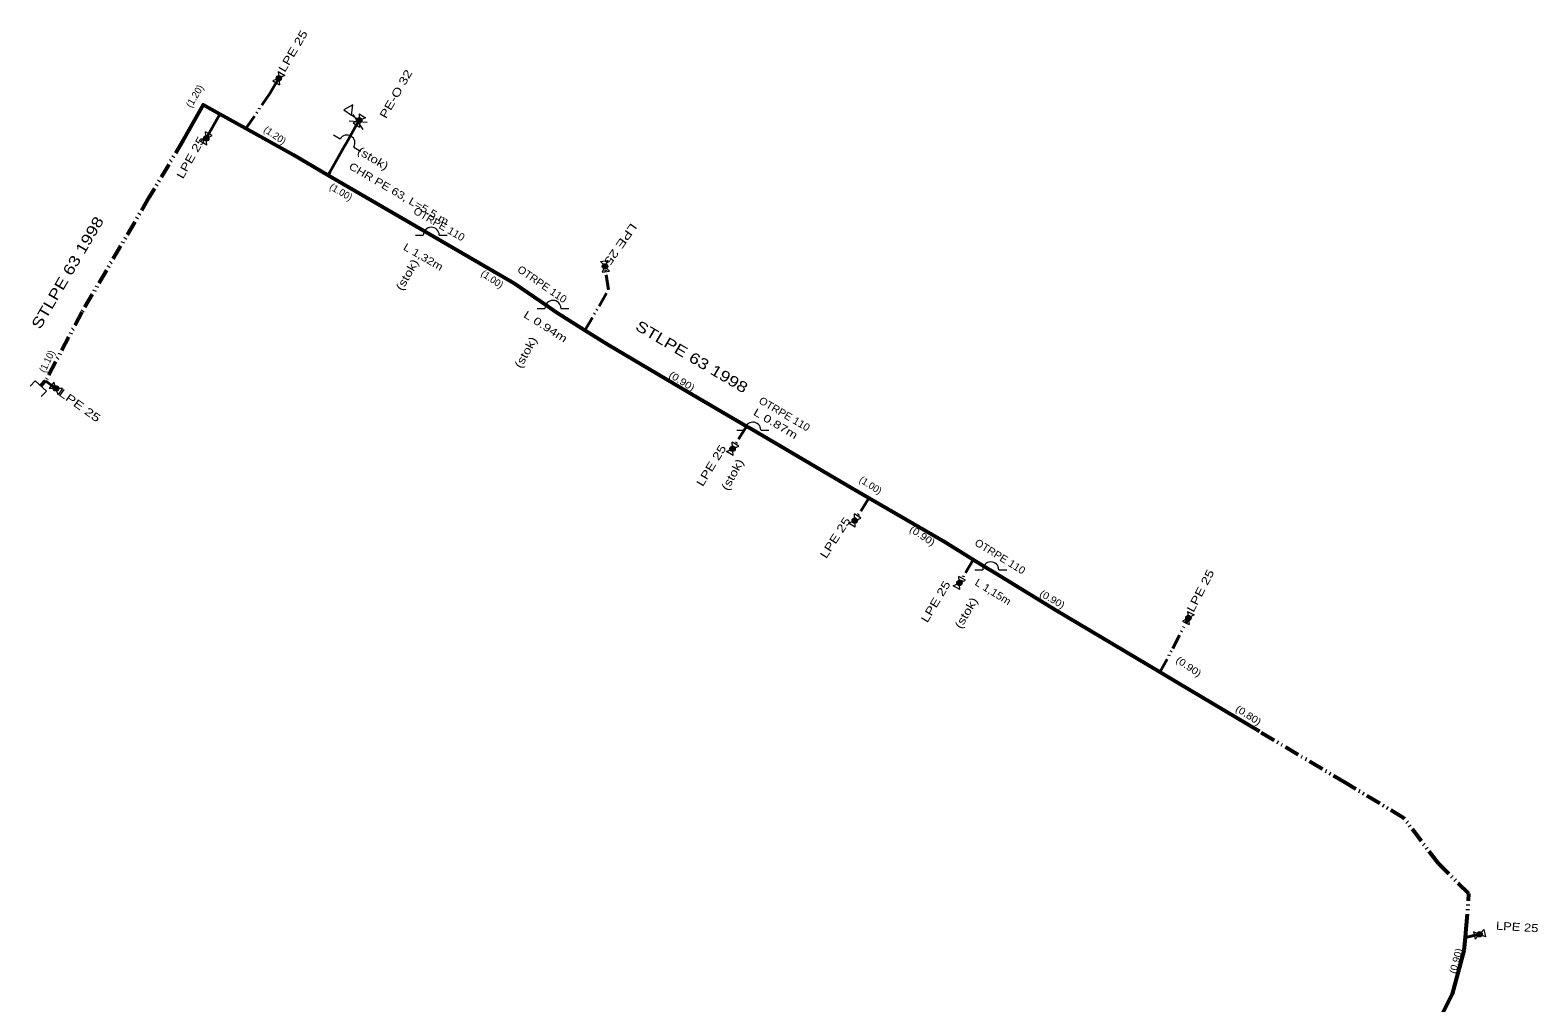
# Model space of a CAD drawing. Extents: x -648036 to -642998, y -1161549 to -1158141.
# Drawn here: x -647414.4 to -647274.3, y -1158231 to -1158140.6 of the extents above; entities that cross this region are included whole.
import ezdxf
from ezdxf.enums import TextEntityAlignment as Align

# ---------------------------------------------------------------- set-up
doc = ezdxf.new("R2010")
doc.units = 0
doc.header["$LTSCALE"] = 0.28
doc.linetypes.add('DASH_DOUBLE_DOT', pattern=[9.2, 5, -1.2, 0.3, -1.2, 0.3, -1.2])
for name, color, linetype, lineweight in [('12', 7, 'DASH_DOUBLE_DOT', 40), ('14', 7, 'Continuous', 13), ('15', 7, 'Continuous', 13), ('19', 7, 'Continuous', 13), ('8', 7, 'Continuous', 53)]:
    doc.layers.add(name, color=color, linetype=linetype, lineweight=lineweight)
for name, color, linetype in [('20', 7, 'Continuous'), ('22', 7, 'Continuous'), ('24', 7, 'Continuous'), ('27', 7, 'Continuous'), ('28', 7, 'Continuous')]:
    doc.layers.add(name, color=color, linetype=linetype)

msp = doc.modelspace()

# ---------------------------------------------------------------- linework, layer by layer
at = {"layer": '12', "linetype": 'Continuous'}
for p, q in [((-647396.79, -1158148.41), (-647398.06, -1158150.68)), ((-647413, -1158173.22), (-647412.03, -1158173.92))]:
    msp.add_line(p, q, dxfattribs=at)
at = {"layer": '12'}
for p, q in [((-647347.84, -1158177.44), (-647349.13, -1158179.53)), ((-647336.46, -1158184.13), (-647337.78, -1158186.2)), ((-647326.77, -1158189.84), (-647328.05, -1158192)), ((-647281, -1158224.94), (-647279.7, -1158224.65))]:
    msp.add_line(p, q, dxfattribs=at)
for points in [[(-647394.38, -1158149.75), (-647392.15, -1158146.51), (-647391.31, -1158145.08)], [(-647362.86, -1158168.52), (-647360.66, -1158164.74), (-647360.99, -1158162.57)], [(-647309.41, -1158200.3), (-647308.22, -1158198.08), (-647306.76, -1158195.25)]]:
    msp.add_lwpolyline(points, dxfattribs=at)
at = {"layer": '12', "linetype": 'Continuous'}
for points in [[(-647386.71, -1158154.12), (-647386.58, -1158153.81), (-647385.16, -1158151.33), (-647385.02, -1158151.08), (-647383.93, -1158149.15)], [(-647383.93, -1158149.15), (-647383.858, -1158149.042), (-647383.83, -1158149)]]:
    msp.add_lwpolyline(points, dxfattribs=at)
at = {"layer": '14'}
for p, q in [((-647376.52, -1158160.05), (-647377.66, -1158159.39)), ((-647365.56, -1158166.82), (-647366.31, -1158166.3)), ((-647346.9, -1158177.99), (-647347.65, -1158177.55)), ((-647324.73, -1158191.1), (-647325.7, -1158190.5))]:
    msp.add_line(p, q, dxfattribs=at)
msp.add_lwpolyline([(-647383.858, -1158149.042), (-647383.93, -1158149.15), (-647385.02, -1158151.08), (-647385.16, -1158151.33), (-647386.58, -1158153.81)], dxfattribs=at)
at = {"layer": '15'}
for p, q in [((-647390.748, -1158144.826), (-647391.872, -1158145.333)), ((-647391.872, -1158145.333), (-647391.258, -1158145.695)), ((-647391.362, -1158144.465), (-647391.258, -1158145.695)), ((-647391.362, -1158144.465), (-647390.748, -1158144.826)), ((-647383.847, -1158148.383), (-647383.813, -1158149.617)), ((-647383.847, -1158148.383), (-647383.254, -1158148.778)), ((-647383.093, -1158149.211), (-647384.766, -1158149.089)), ((-647383.83, -1158149), (-647384.541, -1158148.521)), ((-647383.254, -1158148.778), (-647384.405, -1158149.221)), ((-647384.405, -1158149.221), (-647383.813, -1158149.617)), ((-647383.472, -1158149.853), (-647384.388, -1158148.448)), ((-647398.617, -1158150.946), (-647397.504, -1158150.415)), ((-647397.995, -1158151.294), (-647398.617, -1158150.946)), ((-647397.504, -1158150.415), (-647398.125, -1158150.066)), ((-647397.995, -1158151.294), (-647398.125, -1158150.066)), ((-647386.242, -1158150.347), (-647385.613, -1158150.726)), ((-647384.341, -1158151.495), (-647383.713, -1158151.876)), ((-647378.615, -1158159.685), (-647377.88, -1158159.684)), ((-647376.394, -1158159.684), (-647375.66, -1158159.685)), ((-647361.418, -1158162.125), (-647360.714, -1158162.018)), ((-647361.418, -1158162.125), (-647360.562, -1158163.015)), ((-647360.714, -1158162.018), (-647361.266, -1158163.121)), ((-647361.266, -1158163.121), (-647360.562, -1158163.015)), ((-647367.305, -1158166.475), (-647366.57, -1158166.474)), ((-647365.084, -1158166.474), (-647364.35, -1158166.475)), ((-647412.23, -1158173.337), (-647412.647, -1158173.914)), ((-647411.83, -1158174.504), (-647412.23, -1158173.337)), ((-647411.413, -1158173.926), (-647412.647, -1158173.914)), ((-647411.413, -1158173.926), (-647411.83, -1158174.504)), ((-647348.725, -1158177.795), (-647347.99, -1158177.794)), ((-647346.504, -1158177.794), (-647345.77, -1158177.795)), ((-647348.563, -1158179.289), (-647349.168, -1158178.914)), ((-647349.092, -1158180.146), (-647349.168, -1158178.914)), ((-647349.698, -1158179.772), (-647348.563, -1158179.289)), ((-647349.092, -1158180.146), (-647349.698, -1158179.772)), ((-647338.351, -1158186.434), (-647337.209, -1158185.967)), ((-647337.209, -1158185.967), (-647337.809, -1158185.584)), ((-647337.751, -1158186.816), (-647337.809, -1158185.584)), ((-647337.751, -1158186.816), (-647338.351, -1158186.434)), ((-647328.613, -1158192.252), (-647327.487, -1158191.749)), ((-647327.487, -1158191.749), (-647328.099, -1158191.385)), ((-647328.001, -1158192.615), (-647328.099, -1158191.385)), ((-647326.605, -1158190.785), (-647325.87, -1158190.784)), ((-647324.384, -1158190.784), (-647323.65, -1158190.785)), ((-647328.001, -1158192.615), (-647328.613, -1158192.252)), ((-647306.845, -1158194.639), (-647306.675, -1158195.861)), ((-647306.845, -1158194.639), (-647306.213, -1158194.965)), ((-647306.213, -1158194.965), (-647307.307, -1158195.534)), ((-647307.307, -1158195.534), (-647306.675, -1158195.861)), ((-647280.268, -1158224.412), (-647280.114, -1158225.107)), ((-647279.131, -1158224.888), (-647280.268, -1158224.412)), ((-647279.286, -1158224.193), (-647280.114, -1158225.107)), ((-647279.286, -1158224.193), (-647279.131, -1158224.888))]:
    msp.add_line(p, q, dxfattribs=at)
msp.add_lwpolyline([(-647384.541, -1158148.521), (-647384.422, -1158147.567), (-647385.262, -1158148.035)], close=True, dxfattribs=at)
msp.add_lwpolyline([(-647414.426, -1158173.714), (-647413.946, -1158173.198), (-647412.914, -1158174.162), (-647413.396, -1158174.677)], dxfattribs=at)
for centre, start, end in [((-647384.9774, -1158151.1112), 330.11164, 148.67634), ((-647377.1374, -1158159.6846), 1.2748, 179.83951), ((-647365.8274, -1158166.4746), 1.2748, 179.83951), ((-647347.2474, -1158177.7946), 1.2748, 179.83951), ((-647325.1274, -1158190.7846), 1.2748, 179.83951)]:
    msp.add_arc(centre, 0.7431, start, end, dxfattribs=at)
at = {"layer": '19'}
for centre, radius in [((-647391.31, -1158145.08), 0.25), ((-647391.31, -1158145.08), 0.17), ((-647391.31, -1158145.08), 0.09), ((-647383.83, -1158149), 0.25), ((-647383.83, -1158149), 0.17), ((-647383.83, -1158149), 0.09), ((-647398.06, -1158150.68), 0.25), ((-647398.06, -1158150.68), 0.17), ((-647398.06, -1158150.68), 0.09), ((-647360.99, -1158162.57), 0.25), ((-647360.99, -1158162.57), 0.17), ((-647360.99, -1158162.57), 0.09), ((-647412.03, -1158173.92), 0.25), ((-647412.03, -1158173.92), 0.17), ((-647412.03, -1158173.92), 0.09), ((-647349.13, -1158179.53), 0.25), ((-647349.13, -1158179.53), 0.17), ((-647349.13, -1158179.53), 0.09), ((-647337.78, -1158186.2), 0.25), ((-647337.78, -1158186.2), 0.17), ((-647337.78, -1158186.2), 0.09), ((-647328.05, -1158192), 0.25), ((-647328.05, -1158192), 0.17), ((-647328.05, -1158192), 0.09), ((-647306.76, -1158195.25), 0.25), ((-647306.76, -1158195.25), 0.17), ((-647306.76, -1158195.25), 0.09), ((-647279.7, -1158224.65), 0.25), ((-647279.7, -1158224.65), 0.17), ((-647279.7, -1158224.65), 0.09)]:
    msp.add_circle(centre, radius, dxfattribs=at)
at = {"layer": '8', "linetype": 'DASH_DOUBLE_DOT'}
msp.add_line((-647281.12, -1158226.16), (-647281, -1158224.94), dxfattribs=at)
at = {"layer": '8'}
for points in [[(-647396.79, -1158148.41), (-647398.35, -1158147.57), (-647400.09, -1158150.62), (-647400.21, -1158150.85)], [(-647386.71, -1158154.12), (-647389.99, -1158152.21), (-647394.38, -1158149.75), (-647396.79, -1158148.41)], [(-647362.86, -1158168.52), (-647365.56, -1158166.82), (-647366.31, -1158166.3), (-647369.43, -1158164.15), (-647376.52, -1158160.05), (-647377.66, -1158159.39), (-647386.35, -1158154.33), (-647386.71, -1158154.12)], [(-647347.84, -1158177.44), (-647353.75, -1158173.97), (-647360.68, -1158169.9), (-647362.86, -1158168.52)], [(-647336.46, -1158184.13), (-647338.02, -1158183.23), (-647346.9, -1158177.99), (-647347.65, -1158177.55), (-647347.84, -1158177.44)], [(-647326.77, -1158189.84), (-647329.39, -1158188.22), (-647336.46, -1158184.13)], [(-647309.41, -1158200.3), (-647319.12, -1158194.52), (-647324.73, -1158191.1), (-647325.7, -1158190.5), (-647326.77, -1158189.84)], [(-647300.16, -1158205.81), (-647307.7, -1158201.32), (-647309.41, -1158200.3)], [(-647288.32, -1158243.49), (-647286.21, -1158238.41), (-647285.23, -1158236.21), (-647283.79, -1158233.33), (-647282.2, -1158230.19), (-647281.12, -1158226.16)]]:
    msp.add_lwpolyline(points, dxfattribs=at)
at = {"layer": '8', "linetype": 'DASH_DOUBLE_DOT'}
for points in [[(-647400.21, -1158150.85), (-647403.38, -1158156.17), (-647409.63, -1158166.83), (-647413, -1158173.22), (-647413.43, -1158173.68)], [(-647281, -1158224.94), (-647280.93, -1158224.15), (-647280.68, -1158220.87), (-647283.52, -1158218.08), (-647286.73, -1158213.85), (-647292.07, -1158210.65), (-647300.16, -1158205.81)]]:
    msp.add_lwpolyline(points, dxfattribs=at)

# ---------------------------------------------------------------- texts
at = {"layer": '20', "width": 1.25}
for rotation, p in [(59.588, (-647410.5184, -1158163.4066)), (329.451, (-647353.1751, -1158171.4024))]:
    msp.add_text('STLPE 63 1998', height=1, rotation=rotation, dxfattribs=at).set_placement(p, align=Align.CENTER)
at = {"layer": '22'}
for s, rotation, width, p in [('LPE 25', 59.588, 1.3, (-647389.6717, -1158142.7468)), ('PE-O 32', 60.298, 1.3, (-647380.1012, -1158146.7298)), ('LPE 25', 60.734, 1.3, (-647399.1791, -1158152.6358)), ('LPE 25', 234.913, 1.35, (-647359.849, -1158160.3039)), ('LPE 25', 324.294, 1.35, (-647410.0319, -1158175.8047)), ('LPE 25', 58.442, 1.3, (-647350.7947, -1158181.2793)), ('LPE 25', 57.296, 1.3, (-647339.2768, -1158187.9926)), ('LPE 25', 59.015, 1.3, (-647329.9378, -1158193.9236)), ('LPE 25', 62.452, 1.3, (-647305.3069, -1158192.8909)), ('LPE 25', 356.38, 1.2, (-647276.2207, -1158224.3438))]:
    msp.add_text(s, height=0.75, rotation=rotation, dxfattribs=dict(at, width=width)).set_placement(p, align=Align.CENTER)
at = {"layer": '24'}
for s, rotation, width, p in [('CHR PE 63, L=5.5.m', 329.793, 1.2, (-647380.3251, -1158156.1187)), ('OTRPE 110', 330.024, 1.05, (-647376.5794, -1158158.9407)), ('L 1,32m', 330.024, 1.2, (-647378.0554, -1158161.9909)), ('OTRPE 110', 325.44, 1.05, (-647367.025, -1158164.5194)), ('L 0.94m', 327.732, 1.35, (-647366.7034, -1158168.4624)), ('OTRPE 110', 329.451, 1.05, (-647344.4854, -1158176.5942)), ('L 0.87m', 329.451, 1.35, (-647345.3094, -1158177.4903)), ('OTRPE 110', 328.305, 1.05, (-647324.4469, -1158189.8375)), ('L 1,15m', 328.305, 1.1, (-647325.1004, -1158193.1155))]:
    msp.add_text(s, height=0.7, rotation=rotation, dxfattribs=dict(at, width=width)).set_placement(p, align=Align.CENTER)
at = {"layer": '27'}
for s, rotation, p in [('(1.20)', 59.015, (-647398.8506, -1158146.9113)), ('(1.20)', 326.013, (-647391.8517, -1158150.6424)), ('(1.00)', 329.787, (-647385.6905, -1158155.9285)), ('(1.00)', 326.013, (-647371.6567, -1158164.0189)), ('(1.00)', 327.159, (-647336.4733, -1158183.1739))]:
    msp.add_text(s, height=0.65, rotation=rotation, dxfattribs=at).set_placement(p, align=Align.CENTER)
for s, rotation, width, p in [('(1.10)', 64.171, 0.95, (-647412.566, -1158171.5356)), ('(0.90)', 327.732, 1.15, (-647354.015, -1158173.514)), ('(0.90)', 326.586, 1.15, (-647331.668, -1158187.8802)), ('(0.90)', 330.024, 1.1, (-647319.5784, -1158193.7914)), ('(0.90)', 326.013, 1.15, (-647306.9152, -1158200.0337)), ('(0.80)', 327.159, 1.15, (-647301.3563, -1158204.5579)), ('(0.90)', 75.057, 1.05, (-647281.5848, -1158227.2168))]:
    msp.add_text(s, height=0.65, rotation=rotation, dxfattribs=dict(at, width=width)).set_placement(p, align=Align.CENTER)
at = {"layer": '28', "width": 1.25}
for rotation, p in [(328.837, (-647382.7451, -1158152.8533)), (60.161, (-647379.0519, -1158163.5406)), (60.734, (-647368.0285, -1158170.7448)), (61.306, (-647348.8139, -1158182.107)), (59.588, (-647327.0968, -1158194.9683))]:
    msp.add_text('(stok)', height=0.75, rotation=rotation, dxfattribs=at).set_placement(p, align=Align.CENTER)

doc.saveas('drawing.dxf')
